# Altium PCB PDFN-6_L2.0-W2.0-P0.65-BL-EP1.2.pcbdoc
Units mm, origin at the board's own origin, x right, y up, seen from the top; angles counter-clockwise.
Board outline 14.98 x 15.4 mm, 2 copper layers (Top Layer, Bottom Layer), stack 0 mm thick; 1 components, 0 nets, 8 pads, 0 vias.
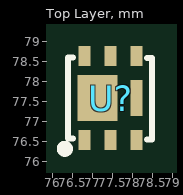
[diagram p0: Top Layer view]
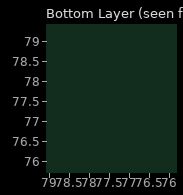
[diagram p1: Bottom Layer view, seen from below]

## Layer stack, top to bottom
Top Layer: signal copper (thickness not stored)
Bottom Layer: signal copper (thickness not stored)

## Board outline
84.834,69.85 69.85,69.85 69.85,85.25 84.834,85.25

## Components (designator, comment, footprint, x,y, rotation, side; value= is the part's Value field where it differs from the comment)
U? "" PDFN-6_L2.0-W2.0-P0.65-BL-EP1.2 77.443,77.597 r0 top

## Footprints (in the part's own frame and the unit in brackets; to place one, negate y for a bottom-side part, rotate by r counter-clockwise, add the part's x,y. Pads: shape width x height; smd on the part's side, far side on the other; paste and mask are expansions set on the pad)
PDFN-6_L2.0-W2.0-P0.65-BL-EP1.2 [mm]
  rect 0.3x0.5 smd: 1(-0.65,-1.053) 2(0,-1.053) 3(0.65,-1.053) 4(0.65,1.053) 5(0,1.053) 6(-0.65,1.053)
  rect 1x1.15 smd: 7(-0.325,0)
  rect 0.3x0.9 smd: 8(0.65,0)
  silkscreen extent -1.24,-1.37 1.04,1.02

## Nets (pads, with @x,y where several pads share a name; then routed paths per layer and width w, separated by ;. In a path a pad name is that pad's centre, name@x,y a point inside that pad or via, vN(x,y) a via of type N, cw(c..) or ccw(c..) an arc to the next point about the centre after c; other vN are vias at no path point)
pads on no net: U?.1 U?.2 U?.3 U?.4 U?.5 U?.6 U?.7 U?.8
